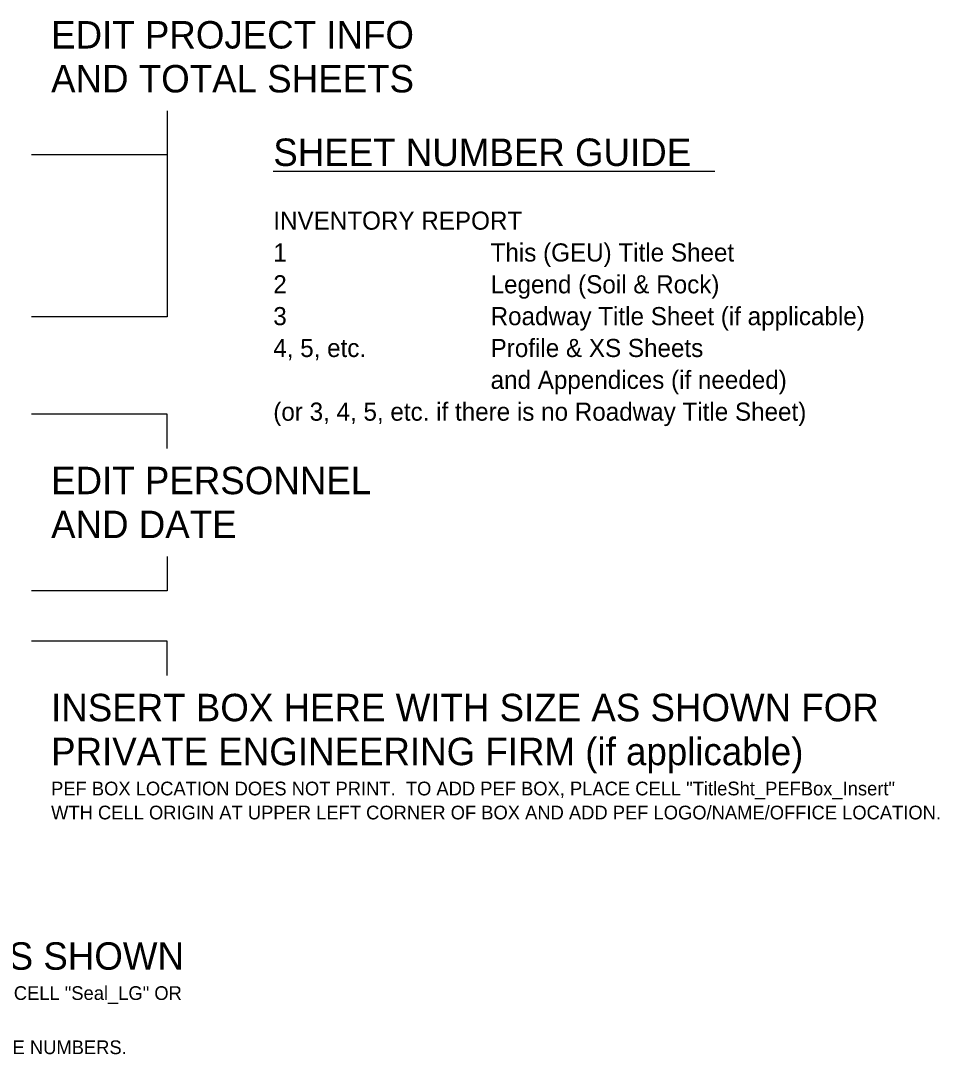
# Model space of a CAD drawing. Extents: x 265553 to 275568, y 168312 to 173522.
# Drawn here: x 274229 to 275568, y 171854 to 173361 of the extents above; entities that cross this region are included whole.
import ezdxf

# ---------------------------------------------------------------- set-up
doc = ezdxf.new("R2010")
doc.units = 0
doc.layers.add('Scratch_Level_4', color=7, linetype='Continuous')
doc.layers.add('Scratch_Level_6', color=7, linetype='Continuous')

msp = doc.modelspace()

# ---------------------------------------------------------------- linework, layer by layer
at = {"layer": 'Scratch_Level_4'}
for points in [[(274442.6, 173229.2), (274442.6, 173165), (274244.5, 173165)], [(274442.6, 173165), (274442.6, 172929.2), (274244.5, 172929.2)], [(274442.6, 172737.2), (274442.6, 172787.2), (274244.5, 172787.2)], [(274442.6, 172579.7), (274442.6, 172529.7), (274244.5, 172529.7)], [(274442.6, 172406.4), (274442.6, 172456.4), (274244.5, 172456.4)]]:
    msp.add_lwpolyline(points, dxfattribs=at)
at = {"layer": 'Scratch_Level_6'}
msp.add_line((275240.6, 173140.6), (274597.1, 173140.6), dxfattribs=at)

# ---------------------------------------------------------------- texts
at = {"layer": 'Scratch_Level_4'}
for s, height, p in [('EDIT PROJECT INFO', 40, (274273.2, 173320)), ('AND TOTAL SHEETS', 40, (274273.2, 173256)), ('EDIT PERSONNEL', 40, (274273.2, 172670.5)), ('AND DATE', 40, (274273.2, 172606.5)), ('INSERT BOX HERE WITH SIZE AS SHOWN FOR', 40, (274273.2, 172339.6)), ('PRIVATE ENGINEERING FIRM (if applicable)', 40, (274273.2, 172275.6)), ('PEF BOX LOCATION DOES NOT PRINT.  TO ADD PEF BOX, PLACE CELL "TitleSht_PEFBox_Insert"', 20, (274273.2, 172231.6)), ('WTH CELL ORIGIN AT UPPER LEFT CORNER OF BOX AND ADD PEF LOGO/NAME/OFFICE LOCATION.', 20, (274273.2, 172196.6)), ('INSERT SEAL(S) HERE WITH SIZE AS SHOWN', 40, (273293, 171977.5)), ('CIRCLES FOR SEAL LOCATIONS DO NOT PRINT.  TO ADD SEAL, PLACE CELL "Seal_LG" OR ', 20, (273293, 171933.5)), ('PE NUMBERS SHOULD BE 6 DIGITS SO ADD A LEADING "0" T0 5 DIGIT PE NUMBERS.', 20, (273293, 171854.5))]:
    msp.add_text(s, height=height, dxfattribs=at).set_placement(p)
at = {"layer": 'Scratch_Level_6'}
for s, height, p in [('SHEET NUMBER GUIDE', 40, (274597.1, 173148.8)), ('INVENTORY REPORT', 26.4, (274597.1, 173056)), ('1', 26.4, (274597.1, 173009.6)), ('This (GEU) Title Sheet', 26.4, (274913.9, 173009.6)), ('2', 26.4, (274597.1, 172963.2)), ('Legend (Soil & Rock)', 26.4, (274913.9, 172963.2)), ('3', 26.4, (274597.1, 172916.8)), ('Roadway Title Sheet (if applicable)', 26.4, (274913.9, 172916.8)), ('4, 5, etc.', 26.4, (274597.1, 172870.4)), ('Profile & XS Sheets', 26.4, (274913.9, 172870.4)), ('and Appendices (if needed)', 26.4, (274913.9, 172824)), ('(or 3, 4, 5, etc. if there is no Roadway Title Sheet)', 26.4, (274597.1, 172777.6))]:
    msp.add_text(s, height=height, dxfattribs=at).set_placement(p)

doc.saveas('drawing.dxf')
